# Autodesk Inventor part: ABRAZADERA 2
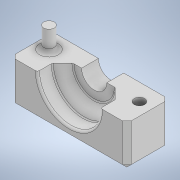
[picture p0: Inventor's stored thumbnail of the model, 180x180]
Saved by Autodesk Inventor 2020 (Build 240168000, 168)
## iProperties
Created: 2022-10
Part Number: ABRAZADERA 2
Material: Genérico
Document SubType Name: Modeling
Designer: SEBAS
Density: 1 g/cm^3
Appearance: Valor por defecto
Author: SEBAS
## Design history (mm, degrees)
sketch "Boceto1"
  geometry: L1 (0, 0)-(0, 24); L2 (0, 0)-(33, 0); L3 (33, 0)-(33, 12); L4 (33, 12)-(23, 12); L5 (23, 12)-(18, 17); L6 (18, 17)-(18, 24); L7 (18, 24)-(0, 24); L8 (33, 0)-(33, 24)
  constraints: 16 end point, 2 horizontal, 2 perpendicular, 2 vertical, 1 horizontal alignment, 1 parallel
  dimensions: "d0" = 24 distance of L1.start L1.end; "d1" = 12 distance of L2.end L3.end; "d2" = 7 distance of L5.end L6.end; "d3" = 18 distance of L6.end L1.end; "d4" = 33 distance between parallel lines of L1 L3; "d5" = 10 distance of L3.end L4.end
revolve "Revolución1" sketch "Boceto1" stored, may be unused: angle "d6" = 180 deg
sketch "Boceto2"
  geometry: L1 (0, 0)-(66, 0) reference; L2 (2, 0)-(64, 0); L3 (64, 0)-(64, 22); L4 (64, 22)-(2, 22); L5 (2, 22)-(2, 0); L6 (11.5, 12)-(54.5, 12); L7 (0, 24)-(66, 24) reference; L8 (0, 0)-(0, 24) reference; L9 (0, 24)-(66, 24); L10 (66, 24)-(66, 0); L11 (66, 0)-(0, 0); L12 (0, 0)-(0, 24); L13 (5.5, 0)-(60.5, 0); L14 (60.5, 0)-(60.5, 20); L15 (60.5, 20)-(5.5, 20); L16 (5.5, 20)-(5.5, 0); C1 r 2.5 at (11.5, 12); C2 r 2.5 at (54.5, 12); 10 further points
  constraints: 26 end point, 6 parallel, 5 midpoint, 4 horizontal, 3 perpendicular, 3 vertical alignment, 2 centre point, 2 point on line, 1 equal radius, 1 horizontal alignment
  dimensions: "d7" = 5 diameter of C1; "d8" = 43 distance of L6.start L6.end; "d9" = 12 distance from line of L7 L6.end; "d10" = 2 distance from line of L1.end L3; "d11" = 2 distance between parallel lines of L7 L4; "d20" = 55 distance of L14.end L15.end; "d21" = 20 distance of L13.end L14.end
extrude "Extrusión1" cut sketch "Boceto2" distance "d12" = 40; taper "d13" = 0 deg
sketch "Boceto3"
  geometry: L1 (46, 0)-(62, 0) reference; L2 (62, 0)-(0, 0); L3 (0, 0)-(0, -20); L4 (0, -20)-(62, -20); L5 (62, -20)-(62, 0); L6 (62, -20)-(0, -20); L7 (0, -20)-(0, -36); L8 (0, -36)-(62, -36); L9 (62, -36)-(62, -20); A1 r 33 centre (31, 0) between (0, -11.314) and (62, -11.314) reference; 5 further points
  constraints: 16 end point, 4 parallel, 2 horizontal, 2 perpendicular, 1 coincident, 1 vertical alignment
  dimensions: "d14" = 20 distance of L4.end L1.end; "d15" = 16 distance between parallel lines of L4 L8
extrude "Extrusión2" cut sketch "Boceto3" stored distance "d16" = 10; taper "d17" = 0 deg
extrude "Extrusión3" join sketch "Boceto3" stored distance "d18" = 10; taper "d19" = 0 deg
extrude "Extrusión4" cut sketch "Boceto2" stored distance "d22" = 10; taper "d23" = 0 deg
extrude "Extrusión5" join sketch "Boceto2" distance "d24" = 10; taper "d25" = 0 deg
extrude "Extrusión6" cut sketch "Boceto2" stored distance "d26" = 10; taper "d27" = 0 deg
fillet "Empalme1" dims "d28" = 2
fillet "Empalme2" dims "d29" = 1
chamfer "Chaflán1" distance "d30" = 2; stored, may be unused: second distance "d31" = 2, angle "d32" = 45 deg
sketch "Boceto4"
  geometry: L1 (0, 0)-(51, 0) reference; C1 r 6 at (25.5, 0); 3 further points
  constraints: 1 centre point, 1 midpoint
  dimensions: "d33" = 12 diameter of C1
extrude "Extrusión7" cut sketch "Boceto4" distance "d34" = 10; taper "d35" = 0 deg
node "Sólido1"
